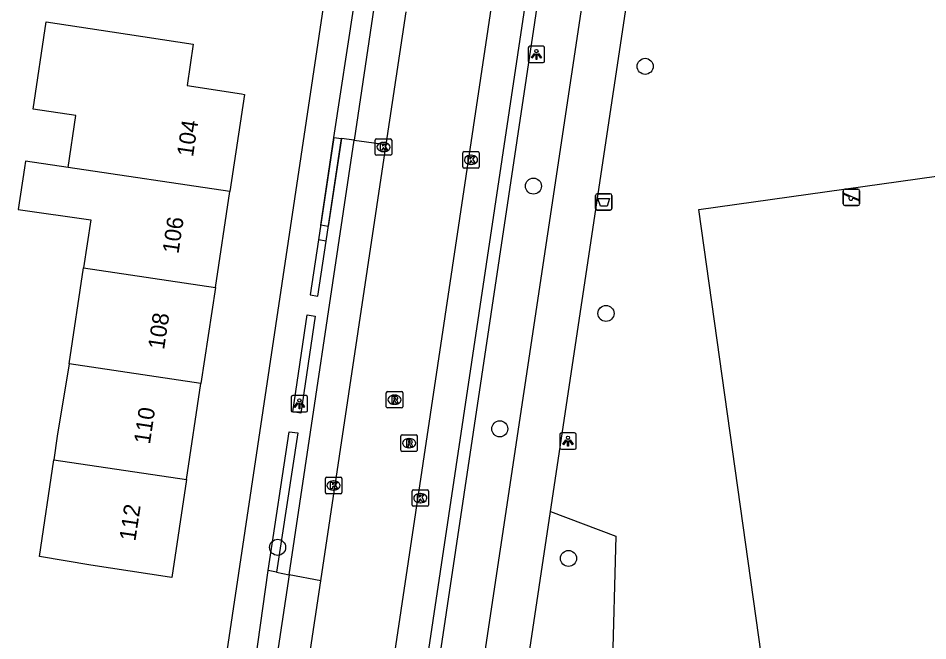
# Model space of a CAD drawing. Extents: x 163010 to 163853, y 382793 to 383982.
# Drawn here: x 163317.2 to 163372.7, y 383072.7 to 383110.7 of the extents above; entities that cross this region are included whole.
import ezdxf

# ---------------------------------------------------------------- set-up
doc = ezdxf.new("R2010")
doc.units = 0
for name, color, linetype in [('IMGEO_Afvalbak', 7, 'Continuous'), ('IMGEO_Boom', 7, 'Continuous'), ('IMGEO_Groenvoorziening', 7, 'Continuous'), ('IMGEO_Haag', 7, 'Continuous'), ('IMGEO_Kolk', 7, 'Continuous'), ('IMGEO_Lichtpunt', 7, 'Continuous'), ('IMGEO_Pand', 7, 'Continuous'), ('IMGEO_Pand_nummerreeks', 7, 'Continuous'), ('IMGEO_Parkeervlak_open', 7, 'Continuous'), ('IMGEO_Rijbaan_lokaal_gesloten', 7, 'Continuous'), ('IMGEO_Rioolput', 7, 'Continuous'), ('IMGEO_Speelvoorziening', 7, 'Continuous'), ('IMGEO_Voetpad_open', 7, 'Continuous')]:
    doc.layers.add(name, color=color, linetype=linetype)

msp = doc.modelspace()

# ---------------------------------------------------------------- linework, layer by layer
at = {"layer": 'IMGEO_Afvalbak'}
for p, q in [((163352.531, 383100), (163353.321, 383100)), ((163353.321, 383100), (163352.531, 383100)), ((163352.431, 383099.1), (163352.431, 383099.9)), ((163352.431, 383099.9), (163352.431, 383099.1)), ((163353.421, 383099.9), (163353.421, 383099.1)), ((163353.421, 383099.1), (163353.421, 383099.9)), ((163353.321, 383099), (163352.531, 383099)), ((163352.531, 383099), (163353.321, 383099))]:
    msp.add_line(p, q, dxfattribs=at)
msp.add_lwpolyline([(163352.574, 383099.714), (163353.278, 383099.714), (163353.129, 383099.244), (163352.723, 383099.244), (163352.574, 383099.714)], dxfattribs=at)
for centre, start, end in [((163352.531, 383099.9), 90, 180), ((163352.531, 383099.9), 90, 180), ((163353.321, 383099.9), 0, 90), ((163353.321, 383099.9), 360, 90), ((163352.531, 383099.1), 180, 270), ((163352.531, 383099.1), 180, 270), ((163353.321, 383099.1), 270, 0), ((163353.321, 383099.1), 270, 0)]:
    msp.add_arc(centre, 0.1, start, end, dxfattribs=at)
at = {"layer": 'IMGEO_Boom'}
for centre in [(163355.454, 383107.769), (163348.639, 383100.465), (163353.064, 383092.7), (163346.584, 383085.66), (163333.039, 383078.432), (163350.777, 383077.757)]:
    msp.add_circle(centre, 0.489, dxfattribs=at)
at = {"layer": 'IMGEO_Groenvoorziening'}
for points in [[(163365.229, 383052.662), (163358.723, 383099.031), (163376.549, 383101.532), (163383.055, 383055.163), (163365.229, 383052.662)], [(163349.687, 383080.612), (163353.657, 383079.124), (163352.328, 383029.091)]]:
    msp.add_lwpolyline(points, dxfattribs=at)
at = {"layer": 'IMGEO_Haag'}
for points in [[(163336.468, 383103.432), (163335.533, 383097.184)], [(163335.991, 383097.115), (163336.93, 383103.375)], [(163335.533, 383097.184), (163335.032, 383093.831)], [(163335.488, 383093.757), (163335.991, 383097.115)]]:
    msp.add_lwpolyline(points, dxfattribs=at)
at = {"layer": 'IMGEO_Kolk'}
for p, q in [((163338.993, 383102.422), (163338.993, 383103.274)), ((163339.068, 383103.348), (163339.92, 383103.348)), ((163339.994, 383103.274), (163339.994, 383102.422)), ((163339.481, 383103.128), (163339.506, 383103.128)), ((163339.92, 383102.348), (163339.068, 383102.348)), ((163339.504, 383102.568), (163339.479, 383102.568)), ((163344.332, 383101.64), (163344.332, 383102.492)), ((163344.407, 383102.566), (163345.259, 383102.566)), ((163344.82, 383102.346), (163344.845, 383102.346)), ((163345.333, 383102.492), (163345.333, 383101.64)), ((163344.843, 383101.786), (163344.818, 383101.786)), ((163345.259, 383101.566), (163344.407, 383101.566)), ((163335.948, 383081.778), (163335.948, 383082.63)), ((163336.023, 383082.704), (163336.875, 383082.704)), ((163336.436, 383082.484), (163336.461, 383082.484)), ((163336.949, 383082.63), (163336.949, 383081.778)), ((163336.875, 383081.704), (163336.023, 383081.704)), ((163336.459, 383081.924), (163336.434, 383081.924)), ((163341.239, 383081.009), (163341.239, 383081.861)), ((163341.314, 383081.935), (163342.166, 383081.935)), ((163341.727, 383081.715), (163341.752, 383081.715)), ((163342.24, 383081.861), (163342.24, 383081.009)), ((163341.75, 383081.155), (163341.725, 383081.155)), ((163342.166, 383080.935), (163341.314, 383080.935))]:
    msp.add_line(p, q, dxfattribs=at)
for points in [[(163338.993, 383102.422), (163338.993, 383103.274)], [(163339.068, 383103.348), (163339.92, 383103.348)], [(163339.994, 383103.274), (163339.994, 383102.422)], [(163339.314, 383103.048), (163339.437, 383103.048), (163339.437, 383102.897), (163339.567, 383103.048), (163339.731, 383103.048), (163339.585, 383102.897), (163339.738, 383102.648), (163339.586, 383102.648), (163339.501, 383102.812), (163339.437, 383102.745), (163339.437, 383102.648), (163339.314, 383102.648), (163339.314, 383103.048)], [(163339.92, 383102.348), (163339.068, 383102.348)], [(163344.332, 383101.64), (163344.332, 383102.492)], [(163344.407, 383102.566), (163345.259, 383102.566)], [(163344.653, 383102.266), (163344.776, 383102.266), (163344.776, 383102.115), (163344.906, 383102.266), (163345.07, 383102.266), (163344.924, 383102.115), (163345.077, 383101.866), (163344.925, 383101.866), (163344.84, 383102.03), (163344.776, 383101.963), (163344.776, 383101.866), (163344.653, 383101.866), (163344.653, 383102.266)], [(163345.333, 383102.492), (163345.333, 383101.64)], [(163345.259, 383101.566), (163344.407, 383101.566)], [(163335.948, 383081.778), (163335.948, 383082.63)], [(163336.023, 383082.704), (163336.875, 383082.704)], [(163336.269, 383082.404), (163336.392, 383082.404), (163336.392, 383082.253), (163336.522, 383082.404), (163336.686, 383082.404), (163336.54, 383082.253), (163336.693, 383082.004), (163336.541, 383082.004), (163336.456, 383082.168), (163336.392, 383082.101), (163336.392, 383082.004), (163336.269, 383082.004), (163336.269, 383082.404)], [(163336.949, 383082.63), (163336.949, 383081.778)], [(163336.875, 383081.704), (163336.023, 383081.704)], [(163341.239, 383081.009), (163341.239, 383081.861)], [(163341.314, 383081.935), (163342.166, 383081.935)], [(163341.56, 383081.635), (163341.683, 383081.635), (163341.683, 383081.484), (163341.813, 383081.635), (163341.977, 383081.635), (163341.831, 383081.484), (163341.984, 383081.235), (163341.832, 383081.235), (163341.747, 383081.399), (163341.683, 383081.332), (163341.683, 383081.235), (163341.56, 383081.235), (163341.56, 383081.635)], [(163342.24, 383081.861), (163342.24, 383081.009)], [(163342.166, 383080.935), (163341.314, 383080.935)]]:
    msp.add_lwpolyline(points, dxfattribs=at)
for centre, start, end in [((163339.07, 383103.272), 91.552, 178.448), ((163339.07, 383103.272), 91.552, 178.448), ((163339.918, 383103.272), 1.552, 88.448), ((163339.918, 383103.272), 1.552, 88.448), ((163339.07, 383102.424), 181.552, 268.448), ((163339.07, 383102.424), 181.552, 268.448), ((163339.918, 383102.424), 271.552, 358.448), ((163339.918, 383102.424), 271.552, 358.448), ((163344.409, 383102.49), 91.552, 178.448), ((163344.409, 383102.49), 91.552, 178.448), ((163345.257, 383102.49), 1.552, 88.448), ((163345.257, 383102.49), 1.552, 88.448), ((163344.409, 383101.642), 181.552, 268.448), ((163344.409, 383101.642), 181.552, 268.448), ((163345.257, 383101.642), 271.552, 358.448), ((163345.257, 383101.642), 271.552, 358.448), ((163336.025, 383082.628), 91.552, 178.448), ((163336.025, 383082.628), 91.552, 178.448), ((163336.873, 383082.628), 1.552, 88.448), ((163336.873, 383082.628), 1.552, 88.448), ((163336.025, 383081.78), 181.552, 268.448), ((163336.025, 383081.78), 181.552, 268.448), ((163336.873, 383081.78), 271.552, 358.448), ((163336.873, 383081.78), 271.552, 358.448), ((163341.316, 383081.859), 91.552, 178.448), ((163341.316, 383081.859), 91.552, 178.448), ((163342.164, 383081.859), 1.552, 88.448), ((163342.164, 383081.859), 1.552, 88.448), ((163341.316, 383081.011), 181.552, 268.448), ((163341.316, 383081.011), 181.552, 268.448), ((163342.164, 383081.011), 271.552, 358.448), ((163342.164, 383081.011), 271.552, 358.448)]:
    msp.add_arc(centre, 0.0765, start, end, dxfattribs=at)
for centre, major_axis, ratio, start_param, end_param in [((163339.48, 383102.848), (-0.387, 0.002), 0.722429, 4.712389, 7.853982), ((163339.505, 383102.848), (-0.39, 0.002), 0.717154, 1.570796, 4.712389), ((163344.819, 383102.066), (-0.387, 0.002), 0.722429, 4.712389, 7.853982), ((163344.844, 383102.066), (-0.39, 0.002), 0.717154, 1.570796, 4.712389), ((163336.435, 383082.204), (-0.387, 0.002), 0.722429, 4.712389, 7.853982), ((163336.46, 383082.204), (-0.39, 0.002), 0.717154, 1.570796, 4.712389), ((163341.726, 383081.435), (-0.387, 0.002), 0.722429, 4.712389, 7.853982), ((163341.751, 383081.435), (-0.39, 0.002), 0.717154, 1.570796, 4.712389)]:
    msp.add_ellipse(centre, major_axis=major_axis, ratio=ratio, start_param=start_param, end_param=end_param, dxfattribs=at)
at = {"layer": 'IMGEO_Lichtpunt'}
for p, q in [((163348.325, 383108.898), (163348.325, 383108.091)), ((163348.325, 383108.898), (163348.325, 383108.091)), ((163349.227, 383108.993), (163348.419, 383108.993)), ((163349.227, 383108.993), (163348.419, 383108.993)), ((163349.321, 383108.091), (163349.321, 383108.898)), ((163349.321, 383108.091), (163349.321, 383108.898)), ((163348.419, 383107.997), (163349.227, 383107.997)), ((163348.419, 383107.997), (163349.227, 383107.997)), ((163333.867, 383087.594), (163333.867, 383086.787)), ((163333.867, 383087.594), (163333.867, 383086.787)), ((163334.769, 383087.689), (163333.961, 383087.689)), ((163334.769, 383087.689), (163333.961, 383087.689)), ((163334.863, 383086.787), (163334.863, 383087.594)), ((163334.863, 383086.787), (163334.863, 383087.594)), ((163333.961, 383086.693), (163334.769, 383086.693)), ((163333.961, 383086.693), (163334.769, 383086.693)), ((163350.247, 383085.317), (163350.247, 383084.51)), ((163350.247, 383085.317), (163350.247, 383084.51)), ((163351.149, 383085.412), (163350.341, 383085.412)), ((163351.149, 383085.412), (163350.341, 383085.412)), ((163351.243, 383084.51), (163351.243, 383085.317)), ((163351.243, 383084.51), (163351.243, 383085.317)), ((163350.341, 383084.416), (163351.149, 383084.416)), ((163350.341, 383084.416), (163351.149, 383084.416))]:
    msp.add_line(p, q, dxfattribs=at)
for points in [[(163348.699, 383108.562), (163348.738, 383108.534), (163348.55, 383108.272), (163348.512, 383108.299), (163348.699, 383108.562)], [(163348.801, 383108.514), (163348.848, 383108.514), (163348.848, 383108.192), (163348.801, 383108.192), (163348.801, 383108.514)], [(163348.911, 383108.534), (163348.949, 383108.561), (163349.136, 383108.299), (163349.097, 383108.271), (163348.911, 383108.534)], [(163334.241, 383087.258), (163334.28, 383087.23), (163334.092, 383086.968), (163334.054, 383086.995), (163334.241, 383087.258)], [(163334.343, 383087.21), (163334.39, 383087.21), (163334.39, 383086.888), (163334.343, 383086.888), (163334.343, 383087.21)], [(163334.453, 383087.23), (163334.491, 383087.257), (163334.678, 383086.995), (163334.639, 383086.967), (163334.453, 383087.23)], [(163350.621, 383084.981), (163350.66, 383084.953), (163350.472, 383084.691), (163350.434, 383084.718), (163350.621, 383084.981)], [(163350.833, 383084.953), (163350.871, 383084.98), (163351.058, 383084.718), (163351.019, 383084.69), (163350.833, 383084.953)], [(163350.723, 383084.933), (163350.77, 383084.933), (163350.77, 383084.611), (163350.723, 383084.611), (163350.723, 383084.933)]]:
    msp.add_lwpolyline(points, dxfattribs=at)
for centre in [(163348.824, 383108.696), (163334.366, 383087.392), (163350.746, 383085.115)]:
    msp.add_circle(centre, 0.0994, dxfattribs=at)
for centre, start, end in [((163348.419, 383108.898), 90, 180), ((163348.419, 383108.898), 90, 180), ((163349.227, 383108.898), 0, 90), ((163349.227, 383108.898), 0, 90), ((163348.419, 383108.091), 180, 270), ((163348.419, 383108.091), 180, 270), ((163349.227, 383108.091), 270, 0), ((163349.227, 383108.091), 270, 360), ((163333.961, 383087.594), 90, 180), ((163333.961, 383087.594), 90, 180), ((163334.769, 383087.594), 0, 90), ((163334.769, 383087.594), 0, 90), ((163333.961, 383086.787), 180, 270), ((163333.961, 383086.787), 180, 270), ((163334.769, 383086.787), 270, 0), ((163334.769, 383086.787), 270, 360), ((163350.341, 383085.317), 90, 180), ((163350.341, 383085.317), 90, 180), ((163351.149, 383085.317), 0, 90), ((163351.149, 383085.317), 0, 90), ((163350.341, 383084.51), 180, 270), ((163350.341, 383084.51), 180, 270), ((163351.149, 383084.51), 270, 0), ((163351.149, 383084.51), 270, 360)]:
    msp.add_arc(centre, 0.0946, start, end, dxfattribs=at)
at = {"layer": 'IMGEO_Pand'}
for points in [[(163320.26, 383101.606), (163320.733, 383104.766), (163318.133, 383105.155), (163318.932, 383110.475), (163322.948, 383109.872), (163327.892, 383109.13), (163327.513, 383106.608), (163330.832, 383106.087), (163331.017, 383106.059), (163330.125, 383100.129)], [(163320.26, 383101.606), (163317.659, 383101.995), (163317.596, 383101.575), (163317.216, 383099.039), (163321.648, 383098.404), (163321.209, 383095.476)], [(163330.125, 383100.129), (163320.26, 383101.606)], [(163329.243, 383094.273), (163330.125, 383100.129)], [(163320.331, 383089.622), (163321.209, 383095.476)], [(163321.209, 383095.476), (163329.243, 383094.273)], [(163329.243, 383094.273), (163328.362, 383088.42)], [(163320.331, 383089.622), (163319.601, 383085.222), (163319.386, 383083.776)], [(163328.362, 383088.42), (163320.331, 383089.622)], [(163327.481, 383082.565), (163328.362, 383088.42)], [(163327.481, 383082.565), (163326.581, 383076.583), (163326.444, 383076.604), (163321.641, 383077.352), (163318.506, 383077.872), (163319.386, 383083.776)], [(163319.386, 383083.776), (163327.481, 383082.565)]]:
    msp.add_lwpolyline(points, dxfattribs=at)
at = {"layer": 'IMGEO_Parkeervlak_open'}
for points in [[(163325.006, 383038.94), (163341.637, 383150.129), (163344.666, 383170.44)], [(163333.742, 383076.759), (163337.702, 383103.259)], [(163336.93, 383103.375), (163336.125, 383098.006), (163335.667, 383098.074), (163336.468, 383103.432)], [(163335.533, 383097.184), (163335.533, 383097.184), (163335.032, 383093.831)], [(163335.991, 383097.115), (163335.533, 383097.184)], [(163335.488, 383093.757), (163335.992, 383097.115), (163335.991, 383097.115)], [(163335.032, 383093.831), (163335.488, 383093.757)], [(163335.327, 383092.538), (163334.448, 383086.618), (163333.966, 383086.701), (163334.844, 383092.615), (163335.327, 383092.538)], [(163332.46, 383077.022), (163333.744, 383085.482), (163334.269, 383085.422), (163332.962, 383076.912)]]:
    msp.add_lwpolyline(points, dxfattribs=at)
at = {"layer": 'IMGEO_Rijbaan_lokaal_gesloten'}
for points in [[(163351.16, 383145.514), (163333.064, 383024.594)], [(163339.666, 383103.012), (163340.877, 383111.094)], [(163335.675, 383076.387), (163339.666, 383103.012)], [(163334.357, 383067.599), (163335.675, 383076.387)]]:
    msp.add_lwpolyline(points, dxfattribs=at)
at = {"layer": 'IMGEO_Rioolput'}
for p, q in [((163339.666, 383087.01), (163339.666, 383087.862)), ((163339.741, 383087.936), (163340.593, 383087.936)), ((163340.667, 383087.862), (163340.667, 383087.01)), ((163340.154, 383087.716), (163340.179, 383087.716)), ((163340.593, 383086.936), (163339.741, 383086.936)), ((163340.177, 383087.156), (163340.152, 383087.156)), ((163340.557, 383084.361), (163340.557, 383085.213)), ((163340.632, 383085.287), (163341.484, 383085.287)), ((163341.045, 383085.067), (163341.07, 383085.067)), ((163341.558, 383085.213), (163341.558, 383084.361)), ((163341.068, 383084.507), (163341.043, 383084.507)), ((163341.484, 383084.287), (163340.632, 383084.287))]:
    msp.add_line(p, q, dxfattribs=at)
for points in [[(163339.666, 383087.01), (163339.666, 383087.862)], [(163339.741, 383087.936), (163340.593, 383087.936)], [(163340.667, 383087.862), (163340.667, 383087.01)], [(163340.255, 383087.634), (163340.003, 383087.636), (163340.003, 383087.236)], [(163340.003, 383087.236), (163340.127, 383087.236), (163340.127, 383087.398), (163340.138, 383087.398)], [(163340.181, 383087.555), (163340.127, 383087.555), (163340.127, 383087.474)], [(163340.127, 383087.474), (163340.179, 383087.474)], [(163340.185, 383087.369), (163340.256, 383087.236), (163340.396, 383087.236), (163340.331, 383087.362)], [(163340.593, 383086.936), (163339.741, 383086.936)], [(163340.557, 383084.361), (163340.557, 383085.213)], [(163340.632, 383085.287), (163341.484, 383085.287)], [(163341.146, 383084.985), (163340.894, 383084.987), (163340.894, 383084.587)], [(163341.558, 383085.213), (163341.558, 383084.361)], [(163340.894, 383084.587), (163341.018, 383084.587), (163341.018, 383084.749), (163341.029, 383084.749)], [(163341.072, 383084.906), (163341.018, 383084.906), (163341.018, 383084.825)], [(163341.018, 383084.825), (163341.07, 383084.825)], [(163341.076, 383084.72), (163341.147, 383084.587), (163341.287, 383084.587), (163341.222, 383084.713)], [(163341.484, 383084.287), (163340.632, 383084.287)]]:
    msp.add_lwpolyline(points, dxfattribs=at)
for centre, radius, start, end in [((163339.743, 383087.86), 0.0765, 91.552, 178.448), ((163339.743, 383087.86), 0.0765, 91.552, 178.448), ((163340.591, 383087.86), 0.0765, 1.552, 88.448), ((163340.591, 383087.86), 0.0765, 1.552, 88.448), ((163340.137, 383087.345), 0.0533, 26.0293, 88.6989), ((163340.163, 383087.663), 0.19, 274.7715, 282.9687), ((163340.187, 383087.459), 0.0964, 77.0061, 93.1865), ((163340.201, 383087.516), 0.0378, 276.6634, 79.6772), ((163340.254, 383087.524), 0.109, 350.3612, 89.416), ((163340.252, 383087.524), 0.112, 277.5842, 350.9817), ((163340.236, 383087.309), 0.108, 29.5134, 73.7905), ((163339.743, 383087.012), 0.0765, 181.552, 268.448), ((163339.743, 383087.012), 0.0765, 181.552, 268.448), ((163340.591, 383087.012), 0.0765, 271.552, 358.448), ((163340.591, 383087.012), 0.0765, 271.552, 358.448), ((163340.634, 383085.211), 0.0765, 91.552, 178.448), ((163340.634, 383085.211), 0.0765, 91.552, 178.448), ((163341.145, 383084.875), 0.109, 350.3612, 89.416), ((163341.482, 383085.211), 0.0765, 1.552, 88.448), ((163341.482, 383085.211), 0.0765, 1.552, 88.448), ((163341.028, 383084.696), 0.0533, 26.0293, 88.6989), ((163341.054, 383085.014), 0.19, 274.7715, 282.9687), ((163341.078, 383084.81), 0.0964, 77.0061, 93.1865), ((163341.092, 383084.867), 0.0378, 276.6634, 79.6772), ((163341.143, 383084.875), 0.112, 277.5842, 350.9817), ((163341.127, 383084.66), 0.108, 29.5134, 73.7905), ((163340.634, 383084.363), 0.0765, 181.552, 268.448), ((163340.634, 383084.363), 0.0765, 181.552, 268.448), ((163341.482, 383084.363), 0.0765, 271.552, 358.448), ((163341.482, 383084.363), 0.0765, 271.552, 358.448)]:
    msp.add_arc(centre, radius, start, end, dxfattribs=at)
for centre, major_axis, ratio, start_param, end_param in [((163340.153, 383087.436), (-0.387, 0.002), 0.722429, 4.712389, 7.853982), ((163340.178, 383087.436), (-0.39, 0.002), 0.717154, 1.570796, 4.712389), ((163341.044, 383084.787), (-0.387, 0.002), 0.722429, 4.712389, 7.853982), ((163341.069, 383084.787), (-0.39, 0.002), 0.717154, 1.570796, 4.712389)]:
    msp.add_ellipse(centre, major_axis=major_axis, ratio=ratio, start_param=start_param, end_param=end_param, dxfattribs=at)
at = {"layer": 'IMGEO_Speelvoorziening'}
for p, q in [((163367.536, 383099.382), (163367.536, 383100.182)), ((163367.536, 383100.182), (163367.536, 383099.382)), ((163367.919, 383099.81), (163367.58, 383099.947)), ((163367.605, 383100.007), (163368.481, 383099.654)), ((163367.636, 383100.282), (163368.426, 383100.282)), ((163368.426, 383100.282), (163367.636, 383100.282)), ((163368.526, 383100.182), (163368.526, 383099.382)), ((163368.526, 383099.382), (163368.526, 383100.182)), ((163368.457, 383099.594), (163368.117, 383099.731)), ((163368.426, 383099.282), (163367.636, 383099.282)), ((163367.636, 383099.282), (163368.426, 383099.282))]:
    msp.add_line(p, q, dxfattribs=at)
for centre, radius, start, end in [((163367.636, 383100.182), 0.1, 90, 180), ((163367.636, 383100.182), 0.1, 90, 180), ((163367.593, 383099.977), 0.0327, 68.078, 248.078), ((163368.426, 383100.182), 0.1, 0, 90), ((163368.426, 383100.182), 0.1, 360, 90), ((163367.636, 383099.382), 0.1, 180, 270), ((163367.636, 383099.382), 0.1, 180, 270), ((163367.998, 383099.72), 0.12, 130.9928, 5.1632), ((163368.426, 383099.382), 0.1, 270, 0), ((163368.426, 383099.382), 0.1, 270, 0), ((163368.469, 383099.624), 0.0327, 248.078, 68.078)]:
    msp.add_arc(centre, radius, start, end, dxfattribs=at)
at = {"layer": 'IMGEO_Voetpad_open'}
for points in [[(163365.957, 383230.31), (163365.933, 383230.19), (163360.066, 383191.606), (163353.723, 383148.969), (163335.498, 383027.101)], [(163354.108, 383146.459), (163356.77, 383146.06), (163342.222, 383049.06), (163339.598, 383049.469)], [(163339.598, 383049.469), (163354.108, 383146.459)], [(163349.687, 383080.612), (163359.394, 383145.384)], [(163336.468, 383103.432), (163337.704, 383111.517)], [(163338.907, 383111.332), (163337.702, 383103.259)], [(163336.468, 383103.432), (163336.93, 383103.375)], [(163337.702, 383103.259), (163336.93, 383103.375)], [(163337.702, 383103.259), (163339.666, 383103.012)], [(163341.294, 383023.84), (163341.722, 383026.543), (163344.847, 383048.321), (163349.687, 383080.612)], [(163331.207, 383068.03), (163332.46, 383077.022)], [(163333.742, 383076.759), (163332.404, 383067.848)], [(163332.962, 383076.912), (163332.46, 383077.022)], [(163332.962, 383076.912), (163333.742, 383076.759)], [(163335.675, 383076.387), (163333.742, 383076.759)]]:
    msp.add_lwpolyline(points, dxfattribs=at)

# ---------------------------------------------------------------- texts
at = {"layer": 'IMGEO_Pand_nummerreeks'}
for s, rotation, p in [('104', 81.4746, (163327.874, 383102.208)), ('106', 81.4746, (163326.989, 383096.303)), ('108', 81.4748, (163326.111, 383090.453)), ('110', 81.4746, (163325.247, 383084.686)), ('112', 81.4748, (163324.361, 383078.776))]:
    msp.add_text(s, height=1, rotation=rotation, dxfattribs=at).set_placement(p)

doc.saveas('drawing.dxf')
